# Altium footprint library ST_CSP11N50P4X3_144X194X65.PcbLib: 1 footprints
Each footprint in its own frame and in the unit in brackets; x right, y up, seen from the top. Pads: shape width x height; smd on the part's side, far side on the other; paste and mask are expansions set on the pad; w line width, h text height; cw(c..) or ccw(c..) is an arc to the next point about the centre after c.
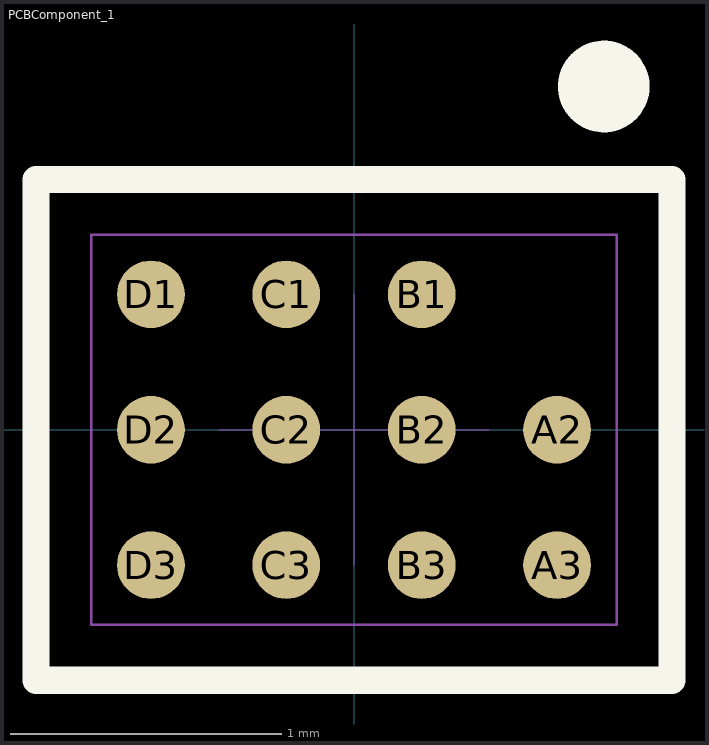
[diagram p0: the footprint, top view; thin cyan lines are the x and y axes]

## PCBComponent_1 [mm]
pads (11):
  round 0.25 smd paste-20 mask+0.045: A2(0.75,0) A3(0.75,-0.5) B1(0.25,0.5) B2(0.25,0) B3(0.25,-0.5) C1(-0.25,0.5) C2(-0.25,0) C3(-0.25,-0.5) D1(-0.75,0.5) D2(-0.75,0) D3(-0.75,-0.5)
Top Overlay:
  circle w0.2: c0.922,1.268 r0.069
  lines w0.1: -1.175,-0.925 -1.175,0.925 1.175,0.925 1.175,-0.925 -1.175,-0.925
Top Paste:
  rectangle: 0.585,-0.665 0.915,-0.335
  rectangle: 0.085,-0.665 0.415,-0.335
  rectangle: -0.415,-0.665 -0.085,-0.335
  rectangle: -0.915,-0.665 -0.585,-0.335
  rectangle: 0.585,-0.165 0.915,0.165
  rectangle: 0.085,-0.165 0.415,0.165
  rectangle: -0.415,-0.165 -0.085,0.165
  rectangle: -0.915,-0.165 -0.585,0.165
  rectangle: 0.085,0.335 0.415,0.665
  rectangle: -0.415,0.335 -0.085,0.665
  rectangle: -0.915,0.335 -0.585,0.665
Mechanical 15:
  lines w0.001: -0.5,0 0.5,0 ; 0,-0.5 0,0.5
  lines w0.01: -0.97,-0.72 -0.97,0.72 0.97,0.72 0.97,-0.72 -0.97,-0.72
3D body: height 0.63, standoff 0.32, extent -0.97,-0.72 0.97,0.72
